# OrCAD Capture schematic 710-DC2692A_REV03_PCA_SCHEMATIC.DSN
size Custom; note: 5/4-CHANNEL, 16/12-BIT, 300/24 mA CURRENT SOURCE DACS WITH 10ppM REFERENCE
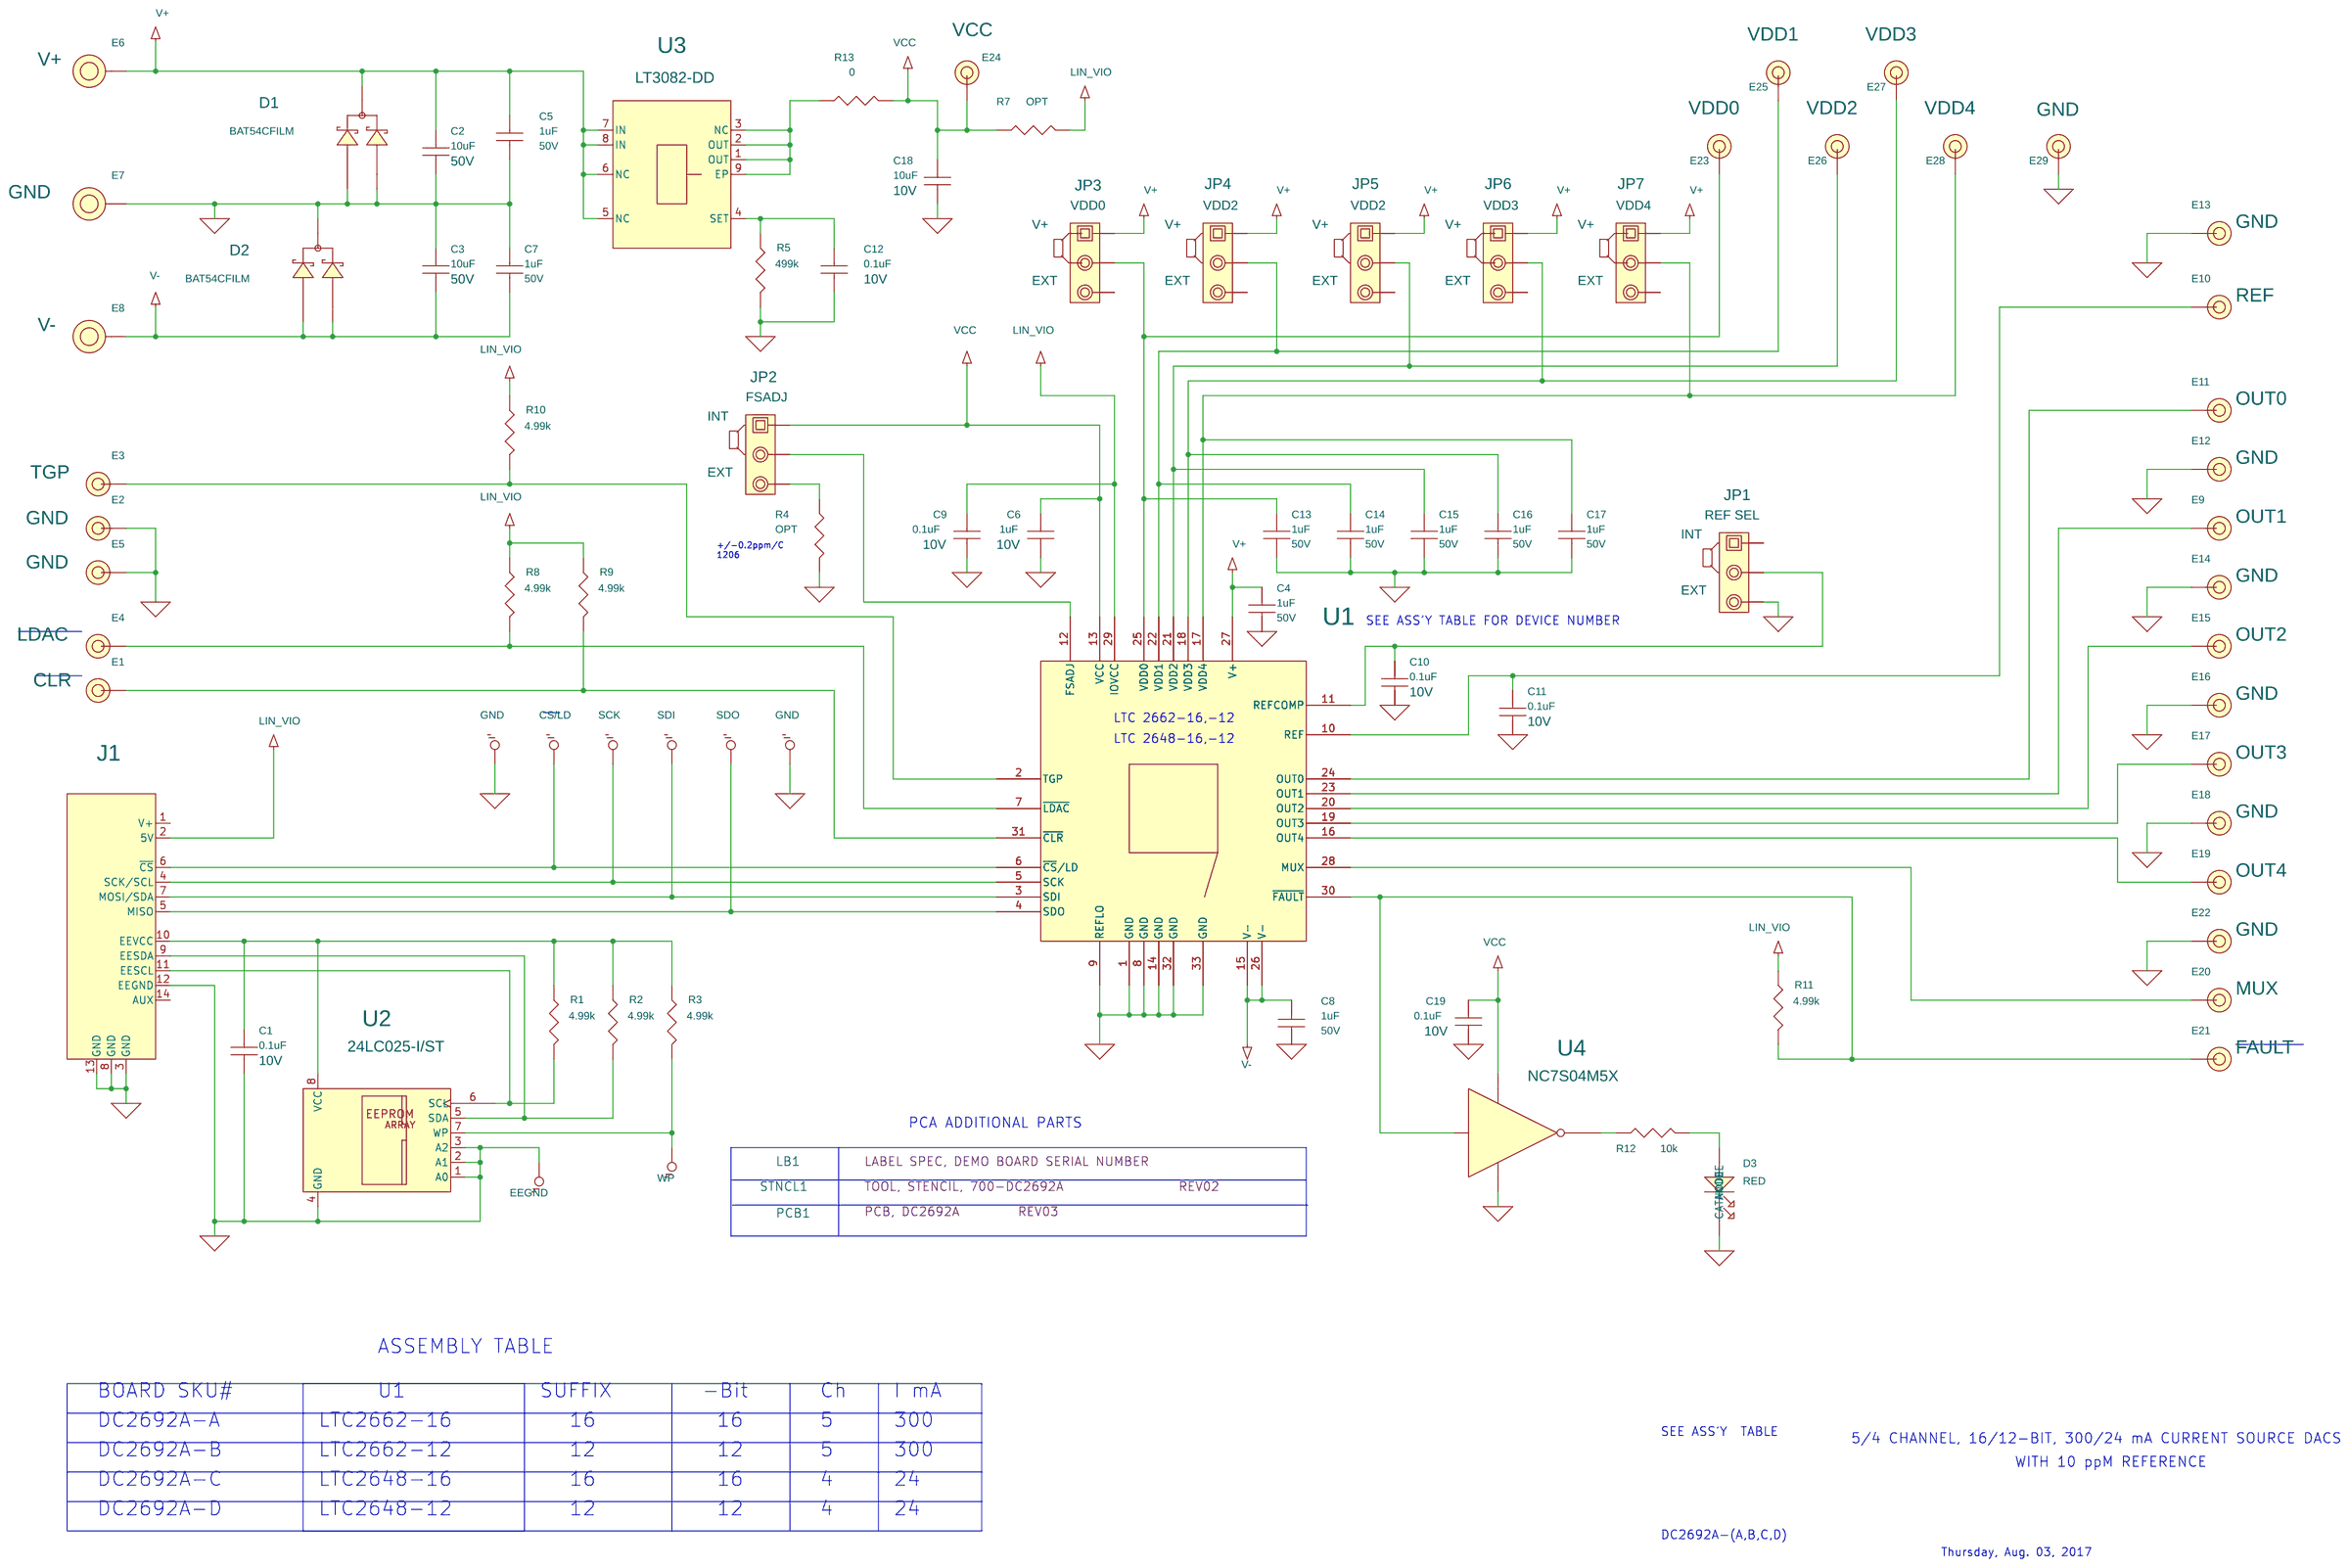
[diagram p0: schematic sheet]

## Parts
C1  0.1uF  [CC0603N]
C2  10uF  [CC1206N]
C3  10uF  [CC1206N]
C4  1uF  [CC0603N]
C5  1uF  [CC0603N]
C6  1uF  [CC0603N]
C7  1uF  [CC0603N]
C8  1uF  [CC0603N]
C9  0.1uF  [CC0603N]
C10  0.1uF  [CC0603N]
C11  0.1uF  [CC0603N]
C12  0.1uF  [CC0603N]
C13  1uF  [CC0603N]
C14  1uF  [CC0603N]
C15  1uF  [CC0603N]
C16  1uF  [CC0603N]
C17  1uF  [CC0603N]
C18  10uF  [CC0603N]
C19  0.1uF  [CC0603N]
D1  BAT54CFILM  [SOT23-3N]
D2  BAT54CFILM  [SOT23-3N]
D3  RED  [LED_0805]
E1  TEST POINT  [MILLMAX2308]
E2  TEST POINT  [MILLMAX2308]
E3  TEST POINT  [MILLMAX2308]
E4  TEST POINT  [MILLMAX2308]
E5  TEST POINT  [MILLMAX2308]
E6  TEST POINT  [MILLMAX2501]
E7  TEST POINT  [MILLMAX2501]
E8  TEST POINT  [MILLMAX2501]
E9  TEST POINT  [MILLMAX2308]
E10  TEST POINT  [MILLMAX2308]
E11  TEST POINT  [MILLMAX2308]
E12  TEST POINT  [MILLMAX2308]
E13  TEST POINT  [MILLMAX2308]
E14  TEST POINT  [MILLMAX2308]
E15  TEST POINT  [MILLMAX2308]
E16  TEST POINT  [MILLMAX2308]
E17  TEST POINT  [MILLMAX2308]
E18  TEST POINT  [MILLMAX2308]
E19  TEST POINT  [MILLMAX2308]
E20  TEST POINT  [MILLMAX2308]
E21  TEST POINT  [MILLMAX2308]
E22  TEST POINT  [MILLMAX2308]
E23  TEST POINT  [MILLMAX2308]
E24  TEST POINT  [MILLMAX2308]
E25  TEST POINT  [MILLMAX2308]
E26  TEST POINT  [MILLMAX2308]
E27  TEST POINT  [MILLMAX2308]
E28  TEST POINT  [MILLMAX2308]
E29  TEST POINT  [MILLMAX2308]
J1  HDR.  [HD2X7-079-MOLEX]
JP1  HDR.  [JP3X1/079]
JP2  HDR.  [JP3X1/079]
JP3  HDR.  [JP3X1/079]
JP4  HDR.  [JP3X1/079]
JP5  HDR.  [JP3X1/079]
JP6  HDR.  [JP3X1/079]
JP7  HDR.  [JP3X1/079]
LB1  LABEL  [895-0154_REV01]
PCB1  PCB, DC2692A
R1  4.99k  [CR0603N]
R2  4.99k  [CR0603N]
R3  4.99k  [CR0603N]
R4  OPT  [CR1206N]
R5  499k  [CR0603N]
R7  OPT  [CR0603N]
R8  4.99k  [CR0603N]
R9  4.99k  [CR0603N]
R10  4.99k  [CR0603N]
R11  4.99k  [CR0603N]
R12  10k  [CR0603N]
R13  0  [CR0603N]
STNCL1  TOOL, STENCIL, 700-DC2692A
TP1  GND  [PCBPAD-60/40]
TP2  CS/LD  [PCBPAD-60/40]
TP3  SCK  [PCBPAD-60/40]
TP4  SDI  [PCBPAD-60/40]
TP5  SDO  [PCBPAD-60/40]
TP6  GND  [PCBPAD-60/40]
TP7  EEGND  [PCBPAD-60/40]
TP8  WP  [PCBPAD-60/40]
U1  LTC2662-UH-16  [LTC-UH-32-1693]
U2  24LC025-I/ST  [MICROCHIP-TSSOP-8]
U3  LT3082-DD  [LTC-DD-8-1698]
U4  NC7S04M5X  [SOT23-5N]
XJP1  SHUNT
XJP2  SHUNT
XJP3  SHUNT
XJP4  SHUNT
XJP5  SHUNT
XJP6  SHUNT
XJP7  SHUNT

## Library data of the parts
C1 C9-C12 C19 = CAP: CAP.,0.1uF,X5R,10V,10%,0603; CLASS: DISCRETE; Dielectric Type: X5R; FPLIST: CC0603N,CC0603L,CC0603M; Manufacturer: AVX; Manufacturer PN: 0603ZD104KAT2A; PART_NUMBER: 150-3154; Package Size: 0603; Rated Voltage: 10V; Tolerance: 10%
C2 C3 = CAP: CAP.,10uF,X5R,50V,10%,1206; CLASS: DISCRETE; Dielectric Type: X5R; FPLIST: CC1206N,CC1206L,CC1206M; Manufacturer: MURATA; Manufacturer PN: GRM31CR61H106KA12L; PART_NUMBER: 150-0330; Package Size: 1206; Rated Voltage: 50V; Tolerance: 10%
C4 C5 C7 C8 C13-C17 = CAP: CAP.,1uF,X5R,50V,10%,0603; CLASS: DISCRETE; Dielectric Type: X5R; FPLIST: CC0603N,CC0603L,CC0603M; Manufacturer: TDK; Manufacturer PN: C1608X5R1H105K080AB; PART_NUMBER: 150-3292; Package Size: 0603; Package Type: SMD; Rated Voltage: 50V; Tolerance: 10%
C6 = CAP: CAP.,1uF,X5R,10V,10%,0603; CLASS: DISCRETE; Dielectric Type: X5R; FPLIST: CC0603N,CC0603L,CC0603M; Manufacturer: AVX; Manufacturer PN: 0603ZD105KAT2A; PART_NUMBER: 150-0113; Package Size: 0603; Rated Voltage: 10V; Tolerance: 10%
C18 = CAP: CAP.,10uF,X5R,10V,20%,0603; CLASS: DISCRETE; Dielectric Type: X5R; FPLIST: CC0603N,CC0603L,CC0603M; Manufacturer: AVX; Manufacturer PN: 0603ZD106MAT2A; PART_NUMBER: 150-3459; Package Size: 0603; Package Type: SMD; Rated Voltage: 10V; Tolerance: 20%
D1 D2 = DIODE_SCHOTTKY_SOT_ARRAY_2: DIODE,SCHOTTKY,40V,300mA,SOT-23; CLASS: DISCRETE; Manufacturer: STMICROELECTRONICS; PART_NUMBER: 210-0248; Package Type: SOT-23; Rated Voltage: 40V
D3 = LED: LED,RED,WATERCLEAR,0805; CLASS: DISCRETE; Manufacturer: WURTH ELEKTRONIK; Manufacturer PN: 150080RS75000; PART_NUMBER: 270-0081; Package Type: 0805
E1 = TEST_POINT_.156_MILL-MAX_2308_B: TEST POINT,TURRET,0.064",MTG. HOLE; CLASS: IO; Manufacturer: MILL-MAX; Manufacturer PN: 2308-2-00-80-00-00-07-0; PART_FIELD_01: CLR; PART_NUMBER: 260-0004
E2 E5 E12-E14 E16 E18 E22 E29 = TEST_POINT_.156_MILL-MAX_2308_B: TEST POINT,TURRET,0.064",MTG. HOLE; CLASS: IO; Manufacturer: MILL-MAX; Manufacturer PN: 2308-2-00-80-00-00-07-0; PART_FIELD_01: GND; PART_NUMBER: 260-0004
E3 = TEST_POINT_.156_MILL-MAX_2308_B: TEST POINT,TURRET,0.064",MTG. HOLE; CLASS: IO; Manufacturer: MILL-MAX; Manufacturer PN: 2308-2-00-80-00-00-07-0; PART_FIELD_01: TGP; PART_NUMBER: 260-0004
E4 = TEST_POINT_.156_MILL-MAX_2308_B: TEST POINT,TURRET,0.064",MTG. HOLE; CLASS: IO; Manufacturer: MILL-MAX; Manufacturer PN: 2308-2-00-80-00-00-07-0; PART_FIELD_01: LDAC; PART_NUMBER: 260-0004
E6 = TESTPOINT_.219_MILL-MAX_2501_A: TEST POINT,TURRET,0.094",MTG. HOLE; CLASS: IO; Manufacturer: MILL-MAX; Manufacturer PN: 2501-2-00-80-00-00-07-0; PART_FIELD_01: V+; PART_NUMBER: 260-0003
E7 = TESTPOINT_.219_MILL-MAX_2501_A: TEST POINT,TURRET,0.094",MTG. HOLE; CLASS: IO; Manufacturer: MILL-MAX; Manufacturer PN: 2501-2-00-80-00-00-07-0; PART_FIELD_01: GND; PART_NUMBER: 260-0003
E8 = TESTPOINT_.219_MILL-MAX_2501_A: TEST POINT,TURRET,0.094",MTG. HOLE; CLASS: IO; Manufacturer: MILL-MAX; Manufacturer PN: 2501-2-00-80-00-00-07-0; PART_FIELD_01: V-; PART_NUMBER: 260-0003
E9 = TEST_POINT_.156_MILL-MAX_2308_B: TEST POINT,TURRET,0.064",MTG. HOLE; CLASS: IO; Manufacturer: MILL-MAX; Manufacturer PN: 2308-2-00-80-00-00-07-0; PART_FIELD_01: OUT1; PART_NUMBER: 260-0004
E10 = TEST_POINT_.156_MILL-MAX_2308_B: TEST POINT,TURRET,0.064",MTG. HOLE; CLASS: IO; Manufacturer: MILL-MAX; Manufacturer PN: 2308-2-00-80-00-00-07-0; PART_FIELD_01: REF; PART_NUMBER: 260-0004
E11 = TEST_POINT_.156_MILL-MAX_2308_B: TEST POINT,TURRET,0.064",MTG. HOLE; CLASS: IO; Manufacturer: MILL-MAX; Manufacturer PN: 2308-2-00-80-00-00-07-0; PART_FIELD_01: OUT0; PART_NUMBER: 260-0004
E15 = TEST_POINT_.156_MILL-MAX_2308_B: TEST POINT,TURRET,0.064",MTG. HOLE; CLASS: IO; Manufacturer: MILL-MAX; Manufacturer PN: 2308-2-00-80-00-00-07-0; PART_FIELD_01: OUT2; PART_NUMBER: 260-0004
E17 = TEST_POINT_.156_MILL-MAX_2308_B: TEST POINT,TURRET,0.064",MTG. HOLE; CLASS: IO; Manufacturer: MILL-MAX; Manufacturer PN: 2308-2-00-80-00-00-07-0; PART_FIELD_01: OUT3; PART_NUMBER: 260-0004
E19 = TEST_POINT_.156_MILL-MAX_2308_B: TEST POINT,TURRET,0.064",MTG. HOLE; CLASS: IO; Manufacturer: MILL-MAX; Manufacturer PN: 2308-2-00-80-00-00-07-0; PART_FIELD_01: OUT4; PART_NUMBER: 260-0004
E20 = TEST_POINT_.156_MILL-MAX_2308_B: TEST POINT,TURRET,0.064",MTG. HOLE; CLASS: IO; Manufacturer: MILL-MAX; Manufacturer PN: 2308-2-00-80-00-00-07-0; PART_FIELD_01: MUX; PART_NUMBER: 260-0004
E21 = TEST_POINT_.156_MILL-MAX_2308_B: TEST POINT,TURRET,0.064",MTG. HOLE; CLASS: IO; Manufacturer: MILL-MAX; Manufacturer PN: 2308-2-00-80-00-00-07-0; PART_FIELD_01: FAULT; PART_NUMBER: 260-0004
E23 = TEST_POINT_.156_MILL-MAX_2308_B: TEST POINT,TURRET,0.064",MTG. HOLE; CLASS: IO; Manufacturer: MILL-MAX; Manufacturer PN: 2308-2-00-80-00-00-07-0; PART_FIELD_01: VDD0; PART_NUMBER: 260-0004
E24 = TEST_POINT_.156_MILL-MAX_2308_B: TEST POINT,TURRET,0.064",MTG. HOLE; CLASS: IO; Manufacturer: MILL-MAX; Manufacturer PN: 2308-2-00-80-00-00-07-0; PART_FIELD_01: VCC; PART_NUMBER: 260-0004
E25 = TEST_POINT_.156_MILL-MAX_2308_B: TEST POINT,TURRET,0.064",MTG. HOLE; CLASS: IO; Manufacturer: MILL-MAX; Manufacturer PN: 2308-2-00-80-00-00-07-0; PART_FIELD_01: VDD1; PART_NUMBER: 260-0004
E26 = TEST_POINT_.156_MILL-MAX_2308_B: TEST POINT,TURRET,0.064",MTG. HOLE; CLASS: IO; Manufacturer: MILL-MAX; Manufacturer PN: 2308-2-00-80-00-00-07-0; PART_FIELD_01: VDD2; PART_NUMBER: 260-0004
E27 = TEST_POINT_.156_MILL-MAX_2308_B: TEST POINT,TURRET,0.064",MTG. HOLE; CLASS: IO; Manufacturer: MILL-MAX; Manufacturer PN: 2308-2-00-80-00-00-07-0; PART_FIELD_01: VDD3; PART_NUMBER: 260-0004
E28 = TEST_POINT_.156_MILL-MAX_2308_B: TEST POINT,TURRET,0.064",MTG. HOLE; CLASS: IO; Manufacturer: MILL-MAX; Manufacturer PN: 2308-2-00-80-00-00-07-0; PART_FIELD_01: VDD4; PART_NUMBER: 260-0004
J1 = CONN_2X7_.079_MOLEX_RIBBON_D: CONN.,HDR.,MALE,2x7,2mm,THT, VERT,SHROUDED; CLASS: IO; Manufacturer: MOLEX; Manufacturer PN: 87831-1420; PART_NUMBER: 250-0403
JP1 = 1X3_A: CONN.,HDR.,MALE,1X3,2mm,THT, STR,SINGLE SOURCE ONLY; 11th Part Field: EXT; 12th Part Field: REF SEL; 9th Part Field: INT; CLASS: IO; Manufacturer: SAMTEC; Manufacturer PN: TMM-103-02-L-S; PART_NUMBER: 250-0638
JP2 = 1X3_A: CONN.,HDR.,MALE,1X3,2mm,THT, STR,SINGLE SOURCE ONLY; 11th Part Field: EXT; 12th Part Field: FSADJ; 9th Part Field: INT; CLASS: IO; Manufacturer: SAMTEC; Manufacturer PN: TMM-103-02-L-S; PART_NUMBER: 250-0638
JP3 = 1X3_A: CONN.,HDR.,MALE,1X3,2mm,THT, STR,SINGLE SOURCE ONLY; 11th Part Field: EXT; 12th Part Field: VDD0; 9th Part Field: V+; CLASS: IO; Manufacturer: SAMTEC; Manufacturer PN: TMM-103-02-L-S; PART_NUMBER: 250-0638
JP4 JP5 = 1X3_A: CONN.,HDR.,MALE,1X3,2mm,THT, STR,SINGLE SOURCE ONLY; 11th Part Field: EXT; 12th Part Field: VDD2; 9th Part Field: V+; CLASS: IO; Manufacturer: SAMTEC; Manufacturer PN: TMM-103-02-L-S; PART_NUMBER: 250-0638
JP6 = 1X3_A: CONN.,HDR.,MALE,1X3,2mm,THT, STR,SINGLE SOURCE ONLY; 11th Part Field: EXT; 12th Part Field: VDD3; 9th Part Field: V+; CLASS: IO; Manufacturer: SAMTEC; Manufacturer PN: TMM-103-02-L-S; PART_NUMBER: 250-0638
JP7 = 1X3_A: CONN.,HDR.,MALE,1X3,2mm,THT, STR,SINGLE SOURCE ONLY; 11th Part Field: EXT; 12th Part Field: VDD4; 9th Part Field: V+; CLASS: IO; Manufacturer: SAMTEC; Manufacturer PN: TMM-103-02-L-S; PART_NUMBER: 250-0638
LB1 = BLANK_LABEL: LABEL SPEC, DEMO BOARD SERIAL NUMBER; Manufacturer: BRADY; Manufacturer PN: THT-96-717-10; PART_NUMBER: 895-0154
PCB1 = BLANK_PCB_PART: BOM Notes: REV03; CLASS: DISCRETE; Manufacturer: MAO BANG; Manufacturer PN: 600-DC2692A; PART_NUMBER: 600-DC2692A
R1-R3 R8-R11 = RES: RES.,4.99k OHMS,1%,1/10W,0603; CLASS: DISCRETE; FPLIST: CR0603N,CR0603L,CR0603M; Manufacturer: PANASONIC; Manufacturer PN: ERJ3EKF4991V; PART_NUMBER: 100-0121; Package Size: 0603; Rated Power: 1/10W; Temperature Coefficient: 100ppm/C; Tolerance: 1%
R4 = RES: RES., OPTION, 1206; BOM Notes: NO STUFF; CLASS: DISCRETE; FPLIST: CR1206N,CR1206L,CR1206M; PART_NUMBER: 100-2459; Package Size: 1206
R5 = RES: RES.,AEC-Q200,499k OHMS,1%,1/10W,0603; CLASS: DISCRETE; FPLIST: CR0603N,CR0603L,CR0603M; Manufacturer: VISHAY; Manufacturer PN: CRCW0603499KFKEA; PART_NUMBER: 100-0122; Package Size: 0603; Rated Power: 1/10W; Temperature Coefficient: 100ppm/C; Tolerance: 1%
R7 = RES: RES., OPTION, 0603; BOM Notes: NO STUFF; CLASS: DISCRETE; FPLIST: CR0603N,CR0603L,CR0603M; PART_NUMBER: 100-2374; Package Size: 0603
R12 = RES: RES.,10k OHMS,1%,1/10W,0603; CLASS: DISCRETE; FPLIST: CR0603N,CR0603L,CR0603M; Manufacturer: NIC; Manufacturer PN: NRC06F1002TRF; PART_NUMBER: 100-2532; Package Size: 0603; Rated Power: 1/10W; Temperature Coefficient: 100ppm/C; Tolerance: 1%
R13 = RES: RES.,0 OHM,1/10W,0603; CLASS: DISCRETE; FPLIST: CR0603N,CR0603L,CR0603M; Manufacturer: VISHAY; Manufacturer PN: CRCW06030000Z0EA; PART_NUMBER: 100-0009; Package Size: 0603; Rated Power: 1/10W
STNCL1 = BLANK_STENCIL_PART: BOM Notes: REV02; CLASS: DISCRETE; Manufacturer: LINEAR TECH.; Manufacturer PN: 830-DC2692A; PART_NUMBER: 830-DC2692A
TP1-TP8 = TESTPOINT_LTC_TEST_JIG: TEST POINT, PCB COPPER FEATURE; PART_NUMBER: LOCAL-001
U1 = LTC2662_2648-UH-X: IC,5-CHANNEL 16-BIT 300 mA CURRENT SOURCE DAC WITH 10 ppM REFERENCE,QFN-32; CLASS: IC; Manufacturer: LINEAR TECH.; Manufacturer PN: LTC2662IUH-16#PBF; PART_NUMBER: LTC2662IUH-16#PBF; Package Type: QFN-32
U2 = 24LC025-I_ST_TSSOP-8_C: IC, MEMORY,EEPROM,2Kb (256x8),TSSOP-8,400kHz; CLASS: IC; Manufacturer: Microchip; PART_NUMBER: 380-0087; Package Size: TSSOP-8; Package Type: TSSOP-8
U3 = LT3082-DD: IC,200mA LDO REGULATOR,DFN-8 (3mmX3mm); CLASS: IC; Manufacturer: LINEAR TECH.; Manufacturer PN: LT3082EDD#PBF; PART_NUMBER: LT3082EDD#PBF; Package Size: DFN-8L; Package Type: DFN-8 (3mmX3mm)
U4 = NC7S04M5X-S0T23-5: IC,TinyLogic HS Inverter,SOT23-5; CLASS: IC; Manufacturer: FAIRCHILD SEMI.; PART_NUMBER: 280-0614; Package Size: SOT23-5; Package Type: SOT23-5
XJP1-XJP7 = SHUNT_2MM: CONN.,SHUNT,FEMALE,2 POS,2mm; CLASS: IO; Manufacturer: SAMTEC; Manufacturer PN: 2SN-BK-G; PART_NUMBER: 250-0419

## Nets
GND_SIGNAL: C1.2 C2.2 C3.1 C4.2 C5.2 C6.2 C7.1 C8.1 C9.2 C10.2 C11.2 C12.2 C13.2 C14.2 C15.2 C16.2 C17.2 C18.2 C19.2 D1.1 D1.2 D2.3 D3.1(CATHODE) E2.1 E5.1 E7.1 E12.1 E13.1 E14.1 E16.1 E18.1 E22.1 E29.1 J1.3(GND) J1.8(GND) J1.12(EEGND) J1.13(GND) JP1.3 R4.2 R5.2 TP1.1 TP6.1 TP7.1 U1.1(GND) U1.8(GND) U1.9(REFLO) U1.14(GND) U1.32(GND) U1.33(GND) U2.1(A0) U2.2(A1) U2.3(A2) U2.4(GND) U4.3
VCC: C6.1 C18.1 C19.1 E24.1 JP2.1 R7.1 R13.2 U1.13(VCC) U4.5
LIN_VIO: C9.1 J1.2(5V) R7.2 R8.1 R9.1 R10.1 R11.1 U1.29(IOVCC)
V+: C2.1 C4.1 C5.1 D1.3 E6.1 JP3.1 JP4.1 JP5.1 JP6.1 JP7.1 U1.27(V+) U3.5(NC) U3.6(NC) U3.7(IN) U3.8(IN)
V-: C3.2 C7.2 C8.2 D2.1 D2.2 E8.1 U1.15(V-) U1.26(V-)
N00384: C1.1 J1.10(EEVCC) R1.1 R2.1 R3.1 U2.8(VCC)
N00495: J1.11(EESCL) R1.2 U2.6(SCL)
N00502: J1.9(EESDA) R2.2 U2.5(SDA)
N00763: R3.2 TP8.1 U2.7(WP)
N988627: J1.5(MISO) TP5.1 U1.4(SDO)
N988639: J1.7(MOSI/SDA) TP4.1 U1.3(SDI)
N988651: J1.4(SCK/SCL) TP3.1 U1.5(SCK)
N988663: J1.6(~{CS}) TP2.1 U1.6(~{CS}/LD)
N990278: E3.1 R10.2 U1.2(TGP)
N992128: C10.1 JP1.2 U1.11(REFCOMP)
N992429: C11.1 E10.1 U1.10(REF)
N992766: E11.1 U1.24(OUT0)
N992778: E9.1 U1.23(OUT1)
N992790: E15.1 U1.20(OUT2)
N992794: E17.1 U1.19(OUT3)
N992822: E19.1 U1.16(OUT4)
N992870: E20.1 U1.28(MUX)
N992898: E21.1 R11.2 U1.30(~{FAULT}) U4.2
N993478: E1.1 R9.2 U1.31(~{CLR})
N993484: C17.1 E28.1 JP7.2 U1.17(VDD4)
N993863: E4.1 R8.2 U1.7(~{LDAC})
N994581: JP2.2 U1.12(FSADJ)
N996930: R13.1 U3.1(OUT) U3.2(OUT) U3.3(NC) U3.9(EP)
N998259: C13.1 E23.1 JP3.2 U1.25(VDD0)
N998271: C14.1 E25.1 JP4.2 U1.22(VDD1)
N998283: C15.1 E26.1 JP5.2 U1.21(VDD2)
N998295: C16.1 E27.1 JP6.2 U1.18(VDD3)
N1012499: C12.1 R5.1 U3.4(SET)
N1016107: JP2.3 R4.1
N1118471: D3.2(ANODE) R12.2
N1118476: R12.1 U4.4

Not connected (* = marked no-connect by the designer): J1 1(V+) 14(AUX); JP1 1; JP3 3; JP4 3; JP5 3; JP6 3; JP7 3

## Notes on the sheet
- +/-0.2ppm/C
  1206
- SEE ASS'Y TABLE FOR DEVICE NUMBER
- LTC 2662-16,-12
- LTC 2648-16,-12
- PCA ADDITIONAL PARTS
- ASSEMBLY TABLE
- BOARD SKU#
- U1
- SUFFIX
- -Bit
- Ch
- I mA
- DC2692A-A
- LTC2662-16
- 16
- 16
- 5
- 300
- SEE ASS'Y  TABLE
- DC2692A-B
- LTC2662-12
- 12
- 12
- 5
- 300
- 5/4 CHANNEL, 16/12-BIT, 300/24 mA CURRENT SOURCE DACS
- WITH 10 ppM REFERENCE
- DC2692A-C
- LTC2648-16
- 16
- 16
- 4
- 24
- DC2692A-D
- LTC2648-12
- 12
- 12
- 4
- 24
- DC2692A-(A,B,C,D)
- Thursday, Aug. 03, 2017
